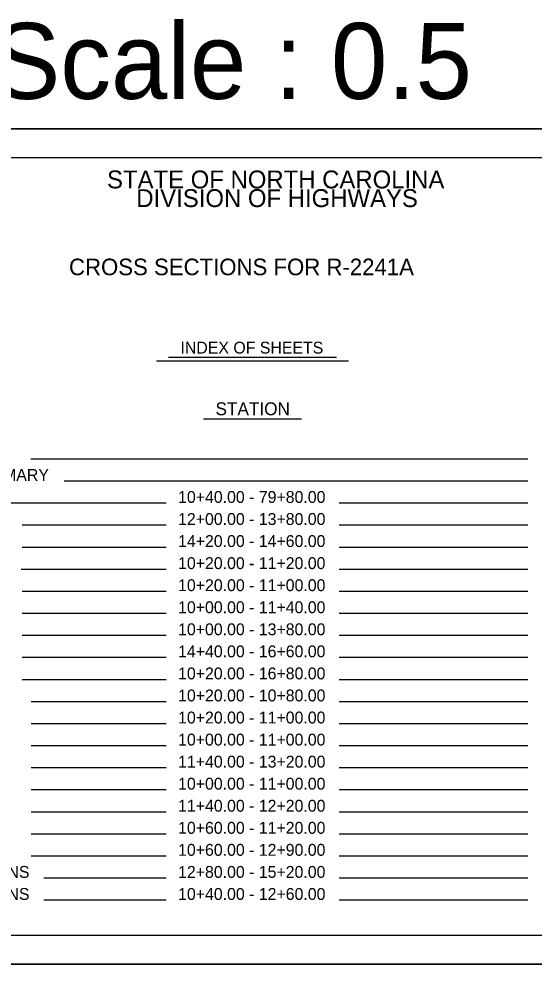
# Model space of a CAD drawing. Extents: x -13516 to -11907, y -4853 to -4486.
# Drawn here: x -12348.1 to -12175.6, y -4802.3 to -4486.2 of the extents above; entities that cross this region are included whole.
import ezdxf

# ---------------------------------------------------------------- set-up
doc = ezdxf.new("R2010")
doc.units = 0
for name, color, linetype in [('Old_Level_2', 7, 'Continuous'), ('Old_Level_44', 7, 'Continuous'), ('Scratch_Level_1', 7, 'Continuous'), ('Sheet Cutting Line CELL', 7, 'Continuous'), ('Sheet Detail CELL', 7, 'Continuous'), ('Sheet Plot Border Outside CELL', 7, 'Continuous')]:
    doc.layers.add(name, color=color, linetype=linetype)

msp = doc.modelspace()

# ---------------------------------------------------------------- linework, layer by layer
at = {"layer": 'Old_Level_2'}
for p, q in [((-12297.97, -4599.31), (-12241.7, -4599.31)), ((-12301.97, -4600.54), (-12237.7, -4600.54)), ((-12286.24, -4619.92), (-12253.42, -4619.92)), ((-12344.11, -4633.3), (-12177.64, -4633.3)), ((-12332.95, -4640.68), (-12177.64, -4640.68)), ((-12350.86, -4648.06), (-12298.77, -4648.06)), ((-12240.89, -4648.06), (-12177.64, -4648.06)), ((-12346.96, -4655.43), (-12298.77, -4655.43)), ((-12240.89, -4655.43), (-12177.64, -4655.43)), ((-12346.96, -4662.81), (-12298.77, -4662.81)), ((-12240.89, -4662.81), (-12177.64, -4662.81)), ((-12347.26, -4670.19), (-12298.77, -4670.19)), ((-12240.89, -4670.19), (-12177.64, -4670.19)), ((-12346.96, -4677.57), (-12298.77, -4677.57)), ((-12240.89, -4677.57), (-12177.64, -4677.57)), ((-12346.96, -4684.94), (-12298.77, -4684.94)), ((-12240.89, -4684.94), (-12177.64, -4684.94)), ((-12346.96, -4692.32), (-12298.77, -4692.32)), ((-12240.89, -4692.32), (-12177.64, -4692.32)), ((-12346.96, -4699.7), (-12298.77, -4699.7)), ((-12240.89, -4699.7), (-12177.64, -4699.7)), ((-12346.96, -4707.08), (-12298.77, -4707.08)), ((-12240.89, -4707.08), (-12177.64, -4707.08)), ((-12343.96, -4714.45), (-12298.77, -4714.45)), ((-12240.89, -4714.45), (-12177.64, -4714.45)), ((-12343.96, -4721.83), (-12298.77, -4721.83)), ((-12240.89, -4721.83), (-12177.64, -4721.83)), ((-12343.96, -4729.21), (-12298.77, -4729.21)), ((-12240.89, -4729.21), (-12177.64, -4729.21)), ((-12343.96, -4736.58), (-12298.77, -4736.58)), ((-12240.89, -4736.58), (-12177.64, -4736.58)), ((-12343.96, -4743.96), (-12298.77, -4743.96)), ((-12240.89, -4743.96), (-12177.64, -4743.96)), ((-12343.96, -4751.34), (-12298.77, -4751.34)), ((-12240.89, -4751.34), (-12177.64, -4751.34)), ((-12343.96, -4758.72), (-12298.77, -4758.72)), ((-12240.89, -4758.72), (-12177.64, -4758.72)), ((-12343.96, -4766.09), (-12298.77, -4766.09)), ((-12240.89, -4766.09), (-12177.64, -4766.09)), ((-12339.77, -4773.47), (-12298.77, -4773.47)), ((-12240.89, -4773.47), (-12177.64, -4773.47)), ((-12339.77, -4780.85), (-12298.77, -4780.85)), ((-12240.89, -4780.85), (-12177.64, -4780.85))]:
    msp.add_line(p, q, dxfattribs=at)
at = {"layer": 'Sheet Cutting Line CELL'}
for p, q in [((-12063.01, -4522.91), (-12494.81, -4522.91)), ((-12494.81, -4802.31), (-12063.01, -4802.31))]:
    msp.add_line(p, q, dxfattribs=at)
at = {"layer": 'Sheet Detail CELL'}
for p, q in [((-12069.36, -4532.61), (-12449.36, -4532.61)), ((-12449.36, -4792.61), (-12069.36, -4792.61))]:
    msp.add_line(p, q, dxfattribs=at)
at = {"layer": 'Sheet Plot Border Outside CELL'}
msp.add_lwpolyline([(-12494.81, -4522.91), (-12063.01, -4522.91), (-12063.01, -4802.31), (-12494.81, -4802.31)], close=True, dxfattribs=at)

# ---------------------------------------------------------------- texts
at = {"layer": 'Old_Level_2'}
for s, height, p in [('INDEX OF SHEETS', 3.9724, (-12293.97, -4598.11)), ('STATION', 4.299, (-12282.24, -4618.72)), ('CROSS-SECTION SUMMARY', 3.9724, (-12410.92, -4640.68)), ('10+40.00 - 79+80.00', 3.9724, (-12294.77, -4648.06)), ('12+00.00 - 13+80.00', 3.9724, (-12294.77, -4655.43)), ('14+20.00 - 14+60.00', 3.9724, (-12294.77, -4662.81)), ('10+20.00 - 11+20.00', 3.9724, (-12294.77, -4670.19)), ('10+20.00 - 11+00.00', 3.9724, (-12294.77, -4677.57)), ('10+00.00 - 11+40.00', 3.9724, (-12294.77, -4684.94)), ('10+00.00 - 13+80.00', 3.9724, (-12294.77, -4692.32)), ('14+40.00 - 16+60.00', 3.9724, (-12294.77, -4699.7)), ('10+20.00 - 16+80.00', 3.9724, (-12294.77, -4707.08)), ('10+20.00 - 10+80.00', 3.9724, (-12294.77, -4714.45)), ('10+20.00 - 11+00.00', 3.9724, (-12294.77, -4721.83)), ('10+00.00 - 11+00.00', 3.9724, (-12294.77, -4729.21)), ('11+40.00 - 13+20.00', 3.9724, (-12294.77, -4736.58)), ('10+00.00 - 11+00.00', 3.9724, (-12294.77, -4743.96)), ('11+40.00 - 12+20.00', 3.9724, (-12294.77, -4751.34)), ('10+60.00 - 11+20.00', 3.9724, (-12294.77, -4758.72)), ('10+60.00 - 12+90.00', 3.9724, (-12294.77, -4766.09)), ('-DET1- CROSS-SECTIONS', 3.9724, (-12410.92, -4773.47)), ('12+80.00 - 15+20.00', 3.9724, (-12294.77, -4773.47)), ('-DET2- CROSS-SECTIONS', 3.9724, (-12410.92, -4780.85)), ('10+40.00 - 12+60.00', 3.9724, (-12294.77, -4780.85))]:
    msp.add_text(s, height=height, rotation=0, dxfattribs=at).set_placement(p)
at = {"layer": 'Old_Level_44'}
for s, p in [('STATE OF NORTH CAROLINA', (-12318.56, -4542.86)), ('DIVISION OF HIGHWAYS', (-12308.76, -4549.11))]:
    msp.add_text(s, height=5.9847, dxfattribs=at).set_placement(p)
msp.add_text('CROSS SECTIONS FOR R-2241A', height=5.55, rotation=0, dxfattribs=at).set_placement((-12331.29, -4571.9))
at = {"layer": 'Scratch_Level_1'}
msp.add_text('Scale : 0.5', height=25.4, dxfattribs=at).set_placement((-12356.87, -4512.92))

doc.saveas('drawing.dxf')
